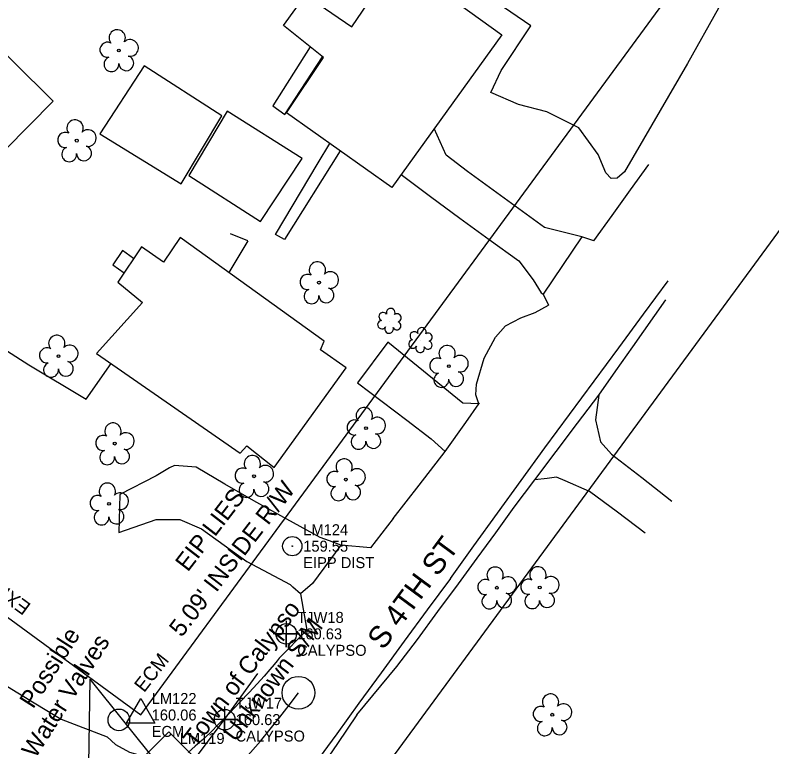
# Model space of a CAD drawing. Extents: x 2262665 to 2270527, y 505476 to 514960.
# Drawn here: x 2266488 to 2266660.4, y 511638.6 to 511805.4 of the extents above; entities that cross this region are included whole.
import ezdxf

# ---------------------------------------------------------------- set-up
doc = ezdxf.new("R2010")
doc.units = 0
for name, color, linetype in [('CTL Secondary Horizontal and Vertical CELL', 7, 'Continuous'), ('CTL Secondary Horizontal and Vertical Cogo Number', 7, 'Continuous'), ('Exist Building', 7, 'Continuous'), ('Exist Building Metal Canopy', 7, 'Continuous'), ('Exist Horizontal Alignment', 7, 'Continuous'), ('Exist Other Culture Area Outline', 7, 'Continuous'), ('Exist Other Culture Fence Line', 7, 'Continuous'), ('Exist Other Culture Gate', 7, 'Continuous'), ('Exist Property Iron Pin CELL', 7, 'Continuous'), ('Exist Property Iron Pin Cogo Comment', 7, 'Continuous'), ('Exist Property Iron Pin Cogo Elevation', 7, 'Continuous'), ('Exist Property Iron Pin Cogo Number', 7, 'Continuous'), ('Exist Property Iron Pin Text', 7, 'Continuous'), ('Exist Right of Way Line', 7, 'Continuous'), ('Exist Right of Way Line Text', 7, 'Continuous'), ('Exist Right of Way Monument CELL', 7, 'Continuous'), ('Exist Right of Way Monument Cogo Comment', 7, 'Continuous'), ('Exist Right of Way Monument Cogo Elevation', 7, 'Continuous'), ('Exist Right of Way Monument Cogo Number', 7, 'Continuous'), ('Exist Right of Way Monument Text', 7, 'Continuous'), ('Exist Roads Change in Surface', 7, 'Continuous'), ('Exist Roads EOP', 7, 'Continuous'), ('Exist Roads EOP Other', 7, 'Continuous'), ('Exist Roads EOP Text', 7, 'Continuous'), ('Exist Roads EOT', 7, 'Continuous'), ('Exist Roads Soil', 7, 'Continuous'), ('Exist Utilities Other Located Object Leader', 7, 'Continuous'), ('Exist Utilities Other Located Object Text', 7, 'Continuous'), ('Exist Utilities Other Pole CELL', 7, 'Continuous'), ('Exist Utilities Water UG Line SUE LOS B', 7, 'Continuous'), ('Exist Utilities Water UG Line SUE LOS B Cogo Comment', 7, 'Continuous'), ('Exist Utilities Water UG Line SUE LOS B Cogo Elevation', 7, 'Continuous'), ('Exist Utilities Water UG Line SUE LOS B Cogo Number', 7, 'Continuous'), ('Exist Utilities Water UG Line SUE LOS B Cogo Point CELL', 7, 'Continuous'), ('Exist Utilities Water UG Line SUE LOS B Text', 7, 'Continuous'), ('Exist Vegetation Shrub CELL', 7, 'Continuous'), ('Exist Vegetation Tree CELL', 7, 'Continuous'), ('Exist Vegetation Woods Line', 7, 'Continuous')]:
    doc.layers.add(name, color=color, linetype=linetype)

msp = doc.modelspace()

# ---------------------------------------------------------------- linework, layer by layer
at = {"layer": 'CTL Secondary Horizontal and Vertical CELL'}
msp.add_lwpolyline([(2266517.74, 511636.81), (2266522.98, 511642.05), (2266528.23, 511636.8), (2266522.99, 511631.56)], close=True, dxfattribs=at)
at = {"layer": 'Exist Building'}
for points in [[(2266573.81, 511766.09), (2266549.82, 511783.07), (2266558.22, 511795.69), (2266549.12, 511802.96), (2266554.14, 511809.94), (2266564.69, 511802.71), (2266575.11, 511818.02), (2266598.82, 511800.85)], [(2266496.61, 511785.73), (2266478.4, 511803.76), (2266467.38, 511793.15), (2266485.72, 511774.63)], [(2266535.06, 511782.39), (2266517.34, 511793.77), (2266507.27, 511778.28), (2266525.78, 511766.89)], [(2266558.39, 511731.07), (2266525.56, 511754.65), (2266521.73, 511749.1), (2266516.74, 511752.54), (2266511.32, 511744.48), (2266516.94, 511739.91), (2266506.52, 511728.23), (2266539.25, 511705.51), (2266540.76, 511707.25), (2266547.01, 511702.31), (2266563.38, 511724.99), (2266557.52, 511729.08)]]:
    msp.add_lwpolyline(points, close=True, dxfattribs=at)
at = {"layer": 'Exist Building Metal Canopy'}
msp.add_lwpolyline([(2266553.37, 511772.67), (2266536.3, 511783.5), (2266527.52, 511768.82), (2266543.83, 511758.33), (2266553.37, 511772.67)], dxfattribs=at)
at = {"layer": 'Exist Horizontal Alignment'}
msp.add_circle((2266552.51, 511650.94), 3.75, dxfattribs=at)
msp.add_arc((2266391.27, 511769.26), 200, 291.7907, 323.7279, dxfattribs=at)
at = {"layer": 'Exist Other Culture Area Outline'}
for points in [[(2266555.2, 511798.11), (2266546.64, 511784.7), (2266549.37, 511782.69), (2266558.01, 511795.86)], [(2266561.99, 511774.46), (2266549.3, 511754.19), (2266547.27, 511755.4), (2266557.01, 511771.71), (2266559.67, 511776.1)], [(2266514.95, 511749.87), (2266512.39, 511751.7), (2266510.22, 511748.42), (2266512.78, 511746.66)]]:
    msp.add_lwpolyline(points, dxfattribs=at)
at = {"layer": 'Exist Other Culture Fence Line'}
msp.add_line((2266540.95, 511753.94), (2266536.66, 511746.68), dxfattribs=at)
msp.add_lwpolyline([(2266466.2, 511742.68), (2266471.66, 511740.59), (2266480.22, 511732.61), (2266491.1, 511725.68), (2266504.15, 511717.81), (2266509.81, 511725.95)], dxfattribs=at)
at = {"layer": 'Exist Other Culture Gate'}
msp.add_line((2266540.95, 511753.94), (2266537, 511755.53), dxfattribs=at)
at = {"layer": 'Exist Property Iron Pin CELL'}
for radius in [2.2, 0.0707]:
    msp.add_circle((2266551.1, 511684.35), radius, dxfattribs=at)
at = {"layer": 'Exist Right of Way Line'}
for p, q in [((2266516.56, 511645.89), (2266751, 511965.37)), ((2266563.3, 511621.69), (2266792.92, 511934.6)), ((2266449.11, 511695.39), (2266516.56, 511645.89))]:
    msp.add_line(p, q, dxfattribs=at)
at = {"layer": 'Exist Right of Way Monument CELL'}
msp.add_line((2266516.56, 511645.89), (2266516.56, 511645.89), dxfattribs=at)
msp.add_lwpolyline([(2266513.31, 511644), (2266516.56, 511649.64), (2266519.81, 511644)], close=True, dxfattribs=at)
at = {"layer": 'Exist Roads Change in Surface'}
for points in [[(2266617.09, 511754.8), (2266612.66, 511748.29), (2266608.23, 511741.78)], [(2266562.19, 511684.61), (2266555.74, 511675.87), (2266552.98, 511673.46)]]:
    msp.add_lwpolyline(points, dxfattribs=at)
at = {"layer": 'Exist Roads EOP'}
for points in [[(2266619.82, 511753.93), (2266623.98, 511759.72), (2266628.14, 511765.51), (2266632.3, 511771.29)], [(2266588.98, 511675.78), (2266593.22, 511681.6), (2266597.45, 511687.41), (2266601.69, 511693.23), (2266606.37, 511699.47), (2266611.22, 511705.91), (2266616.06, 511712.35), (2266620.91, 511718.78), (2266624.81, 511724.29), (2266628.7, 511729.79), (2266636.2, 511740.46)], [(2266574.07, 511690.66), (2266580, 511698.28), (2266585.93, 511705.9), (2266590.61, 511712.55), (2266593.61, 511716.79), (2266593.74, 511716.98)], [(2266574.07, 511690.66), (2266568.95, 511683.96)], [(2266565.81, 511645.9), (2266565.81, 511645.9), (2266574.94, 511656.91), (2266579.63, 511663.09), (2266584.3, 511669.43), (2266588.98, 511675.78)], [(2266554.39, 511665.22), (2266548.14, 511658.81), (2266548.14, 511658.81)], [(2266548.14, 511658.81), (2266547.69, 511658.25), (2266546.97, 511657.38), (2266545.96, 511656.22), (2266544.66, 511654.74), (2266543.09, 511653), (2266541.26, 511651.01), (2266539.16, 511648.79), (2266536.8, 511646.32), (2266534.44, 511643.91), (2266532.36, 511641.85), (2266530.54, 511640.14), (2266529, 511638.79), (2266527.35, 511637.37)], [(2266565.81, 511645.9), (2266561.38, 511639.4), (2266557.58, 511633.86), (2266554.41, 511629.27), (2266549.65, 511622.49), (2266549.53, 511622.32)]]:
    msp.add_lwpolyline(points, dxfattribs=at)
at = {"layer": 'Exist Roads EOP Other'}
msp.add_line((2266568.95, 511683.96), (2266562.19, 511684.61), dxfattribs=at)
for points in [[(2266619.82, 511753.93), (2266617.09, 511754.8), (2266608.59, 511756.96), (2266602.73, 511761.22), (2266596.88, 511765.47), (2266591.03, 511769.73), (2266586.17, 511773.41), (2266583.46, 511779.5)], [(2266575.92, 511769.02), (2266582.6, 511764.04), (2266589.28, 511759.07), (2266595.99, 511754.21), (2266602.69, 511749.36), (2266605.97, 511745.06), (2266607.78, 511742.05), (2266608.23, 511741.78), (2266609.5, 511739.28)], [(2266593.61, 511716.79), (2266592.95, 511718.81), (2266593.05, 511721.25), (2266594.81, 511727.16), (2266597.41, 511731.98), (2266599.7, 511734.53), (2266603.2, 511736.39), (2266606.44, 511737.61), (2266609.5, 511739.28)], [(2266552.98, 511673.46), (2266554.39, 511665.22)]]:
    msp.add_lwpolyline(points, dxfattribs=at)
at = {"layer": 'Exist Roads EOT'}
for points in [[(2266587.12, 511677.01), (2266592.5, 511684.45), (2266597.88, 511691.88), (2266603.26, 511699.32), (2266608.64, 511706.76), (2266614.26, 511714.37), (2266619.88, 511721.97), (2266625.51, 511729.58), (2266631.13, 511737.19), (2266636.76, 511744.79)], [(2266587.12, 511677.01), (2266581.86, 511669.84), (2266576.61, 511662.67), (2266571.35, 511655.5), (2266566.29, 511648.56), (2266561.22, 511641.61), (2266556.16, 511634.67), (2266551.09, 511627.72), (2266548.04, 511623.6)]]:
    msp.add_lwpolyline(points, dxfattribs=at)
at = {"layer": 'Exist Roads Soil'}
for p, q in [((2266562.19, 511684.61), (2266562.19, 511684.61)), ((2266552.98, 511673.46), (2266551.25, 511675.03))]:
    msp.add_line(p, q, dxfattribs=at)
for points in [[(2266593.61, 511716.79), (2266589.95, 511716.94), (2266584.25, 511721.56), (2266578.55, 511726.19), (2266572.84, 511730.81), (2266565.97, 511721.56), (2266571.57, 511717.31), (2266577.18, 511713.05), (2266582.78, 511708.8), (2266585.93, 511705.9)], [(2266620.91, 511718.78), (2266620.19, 511713.14), (2266621.34, 511708.09), (2266623.85, 511705.31), (2266630.73, 511699.96), (2266637.6, 511694.6)], [(2266562.19, 511684.61), (2266559.61, 511685.55), (2266557.43, 511686.35), (2266549.87, 511690.51), (2266542.32, 511694.68), (2266535.74, 511698.5), (2266529.17, 511702.32), (2266524.28, 511702.7), (2266523.11, 511702.19), (2266520.1, 511700.4)], [(2266520.1, 511700.4), (2266511.81, 511696.15), (2266511.58, 511687.5), (2266520.12, 511690.41), (2266525.5, 511690.42), (2266530.4, 511688.29), (2266540.78, 511680.85), (2266550.64, 511675.59), (2266551.25, 511675.03)], [(2266631.53, 511687.35), (2266625.18, 511692.08), (2266618.83, 511696.8), (2266613.25, 511699.26), (2266611.33, 511700.05), (2266609.14, 511699.75), (2266606.37, 511699.47)], [(2266465.71, 511662.82), (2266470.41, 511659.42), (2266478.29, 511655.89), (2266486.18, 511652.36), (2266492.31, 511648.66), (2266498.44, 511644.96), (2266508.95, 511640.94)], [(2266508.95, 511640.94), (2266510.82, 511639.18), (2266514.01, 511637.42), (2266516.96, 511636.54), (2266519.34, 511636.1), (2266522.03, 511635.87), (2266525.83, 511636.42)]]:
    msp.add_lwpolyline(points, dxfattribs=at)
at = {"layer": 'Exist Utilities Other Located Object Leader'}
for p in [(2266504.33, 511608.41), (2266532.76, 511619.63)]:
    msp.add_line(p, (2266505.05, 511654.01), dxfattribs=at)
at = {"layer": 'Exist Utilities Other Pole CELL'}
msp.add_circle((2266511.59, 511644.77), 2.46, dxfattribs=at)
at = {"layer": 'Exist Utilities Water UG Line SUE LOS B'}
msp.add_lwpolyline([(2266489.05, 511579.09), (2266496.16, 511589.74), (2266506.6, 511604.6), (2266522.73, 511627.69), (2266535.69, 511644.83), (2266543.26, 511655.36)], dxfattribs=at)
at = {"layer": 'Exist Utilities Water UG Line SUE LOS B Cogo Point CELL'}
for points in [[(2266549.73, 511667.37), (2266549.73, 511661.37), (2266549.73, 511664.37), (2266552.73, 511664.37), (2266546.73, 511664.37)], [(2266535.69, 511647.83), (2266535.69, 511641.83), (2266535.69, 511644.83), (2266538.69, 511644.83), (2266532.69, 511644.83)]]:
    msp.add_lwpolyline(points, dxfattribs=at)
for centre in [(2266549.73, 511664.37), (2266535.69, 511644.83)]:
    msp.add_circle(centre, 2.34, dxfattribs=at)
at = {"layer": 'Exist Vegetation Shrub CELL'}
for p, q in [((2266573.29, 511735.51), (2266573.29, 511735.51)), ((2266580.37, 511731.11), (2266580.37, 511731.11))]:
    msp.add_line(p, q, dxfattribs=at)
for centre, radius, start, end in [((2266573.52, 511737.55), 0.99, 334.8391, 200.4717), ((2266571.81, 511736.64), 0.968, 35.8908, 245.4216), ((2266574.97, 511736.38), 0.929, 284.4567, 126.0861), ((2266571.49, 511734.81), 0.955, 95.1099, 327.9534), ((2266574.93, 511734.58), 0.937, 204.9913, 73.4601), ((2266573.17, 511733.83), 0.984, 151.2797, 21.387), ((2266578.89, 511732.24), 0.968, 35.8908, 245.4216), ((2266580.6, 511733.15), 0.99, 334.8391, 200.4717), ((2266582.04, 511731.98), 0.929, 284.4567, 126.0861), ((2266578.57, 511730.4), 0.955, 95.1099, 327.9534), ((2266582.01, 511730.18), 0.937, 204.9913, 73.4601), ((2266580.24, 511729.43), 0.984, 151.2797, 21.387)]:
    msp.add_arc(centre, radius, start, end, dxfattribs=at)
at = {"layer": 'Exist Vegetation Tree CELL'}
for p, q in [((2266511.59, 511797.29), (2266511.59, 511797.29)), ((2266501.98, 511776.75), (2266501.98, 511776.75)), ((2266557.19, 511744.4), (2266557.19, 511744.4)), ((2266497.84, 511727.66), (2266497.84, 511727.66)), ((2266586.76, 511725.35), (2266586.76, 511725.35)), ((2266567.9, 511711.23), (2266567.9, 511711.23)), ((2266510.64, 511707.71), (2266510.64, 511707.71)), ((2266542.39, 511700.28), (2266542.39, 511700.28)), ((2266563.3, 511699.51), (2266563.3, 511699.51)), ((2266509.35, 511694), (2266509.35, 511694)), ((2266597.71, 511674.88), (2266597.71, 511674.88)), ((2266607.47, 511674.93), (2266607.47, 511674.93)), ((2266610.33, 511645.95), (2266610.33, 511645.95))]:
    msp.add_line(p, q, dxfattribs=at)
for centre in [(2266511.59, 511797.29), (2266501.98, 511776.75), (2266557.19, 511744.4), (2266497.84, 511727.66), (2266586.76, 511725.35), (2266567.9, 511711.23), (2266510.64, 511707.71), (2266542.39, 511700.28), (2266563.3, 511699.51), (2266509.35, 511694), (2266597.71, 511674.88), (2266607.47, 511674.93), (2266610.33, 511645.95)]:
    msp.add_circle(centre, 0.326, dxfattribs=at)
for centre, radius, start, end in [((2266511.21, 511800.17), 1.86, 330.1651, 219.7134), ((2266508.99, 511797.45), 1.73, 62.6636, 279.3457), ((2266514.14, 511797.88), 1.9, 257.1011, 134.1999), ((2266509.89, 511794.17), 1.69, 111.5671, 6.231), ((2266513.27, 511794.39), 1.7, 181.2822, 74.56), ((2266501.6, 511779.63), 1.86, 330.1651, 219.7134), ((2266499.38, 511776.91), 1.73, 62.6636, 279.3457), ((2266504.53, 511777.34), 1.9, 257.1011, 134.1999), ((2266500.28, 511773.63), 1.69, 111.5671, 6.231), ((2266503.66, 511773.86), 1.7, 181.2822, 74.56), ((2266556.81, 511747.28), 1.86, 330.1651, 219.7134), ((2266559.74, 511744.99), 1.9, 257.1011, 134.1999), ((2266554.59, 511744.56), 1.73, 62.6636, 279.3457), ((2266558.87, 511741.51), 1.7, 181.2822, 74.56), ((2266555.49, 511741.28), 1.69, 111.5671, 6.231), ((2266497.45, 511730.54), 1.86, 330.1651, 219.7134), ((2266495.23, 511727.82), 1.73, 62.6636, 279.3457), ((2266500.39, 511728.25), 1.9, 257.1011, 134.1999), ((2266586.38, 511728.22), 1.86, 330.1651, 219.7134), ((2266589.31, 511725.94), 1.9, 257.1011, 134.1999), ((2266496.13, 511724.54), 1.69, 111.5671, 6.231), ((2266499.51, 511724.76), 1.7, 181.2822, 74.56), ((2266584.16, 511725.5), 1.73, 62.6636, 279.3457), ((2266585.06, 511722.23), 1.69, 111.5671, 6.231), ((2266588.43, 511722.45), 1.7, 181.2822, 74.56), ((2266567.51, 511714.11), 1.86, 330.1651, 219.7134), ((2266510.25, 511710.58), 1.86, 330.1651, 219.7134), ((2266565.29, 511711.39), 1.73, 62.6636, 279.3457), ((2266570.45, 511711.82), 1.9, 257.1011, 134.1999), ((2266508.03, 511707.86), 1.73, 62.6636, 279.3457), ((2266513.19, 511708.3), 1.9, 257.1011, 134.1999), ((2266566.19, 511708.11), 1.69, 111.5671, 6.231), ((2266569.57, 511708.33), 1.7, 181.2822, 74.56), ((2266508.93, 511704.59), 1.69, 111.5671, 6.231), ((2266512.31, 511704.81), 1.7, 181.2822, 74.56), ((2266542, 511703.15), 1.86, 330.1651, 219.7134), ((2266562.92, 511702.38), 1.86, 330.1651, 219.7134), ((2266539.78, 511700.43), 1.73, 62.6636, 279.3457), ((2266544.94, 511700.86), 1.9, 257.1011, 134.1999), ((2266565.85, 511700.1), 1.9, 257.1011, 134.1999), ((2266560.7, 511699.66), 1.73, 62.6636, 279.3457), ((2266508.96, 511696.88), 1.86, 330.1651, 219.7134), ((2266540.68, 511697.16), 1.69, 111.5671, 6.231), ((2266544.06, 511697.38), 1.7, 181.2822, 74.56), ((2266564.97, 511696.61), 1.7, 181.2822, 74.56), ((2266561.6, 511696.39), 1.69, 111.5671, 6.231), ((2266506.74, 511694.16), 1.73, 62.6636, 279.3457), ((2266511.9, 511694.59), 1.9, 257.1011, 134.1999), ((2266507.64, 511690.88), 1.69, 111.5671, 6.231), ((2266511.02, 511691.1), 1.7, 181.2822, 74.56), ((2266597.32, 511677.75), 1.86, 330.1651, 219.7134), ((2266607.08, 511677.81), 1.86, 330.1651, 219.7134), ((2266595.1, 511675.03), 1.73, 62.6636, 279.3457), ((2266600.26, 511675.47), 1.9, 257.1011, 134.1999), ((2266604.86, 511675.09), 1.73, 62.6636, 279.3457), ((2266610.02, 511675.52), 1.9, 257.1011, 134.1999), ((2266596, 511671.76), 1.69, 111.5671, 6.231), ((2266599.38, 511671.98), 1.7, 181.2822, 74.56), ((2266605.77, 511671.81), 1.69, 111.5671, 6.231), ((2266609.14, 511672.04), 1.7, 181.2822, 74.56), ((2266609.94, 511648.83), 1.86, 330.1651, 219.7134), ((2266612.88, 511646.54), 1.9, 257.1011, 134.1999), ((2266607.72, 511646.11), 1.73, 62.6636, 279.3457), ((2266608.62, 511642.83), 1.69, 111.5671, 6.231), ((2266612, 511643.06), 1.7, 181.2822, 74.56)]:
    msp.add_arc(centre, radius, start, end, dxfattribs=at)
at = {"layer": 'Exist Vegetation Woods Line'}
msp.add_lwpolyline([(2266648.19, 511806.95), (2266641.12, 511794.35), (2266626.77, 511769.66), (2266625.15, 511768.17), (2266623.72, 511768.16), (2266622.57, 511769.45), (2266620.77, 511773.62), (2266616.38, 511779.67), (2266609.08, 511783.34), (2266602.66, 511784.97), (2266596.36, 511787.75), (2266598.71, 511792.74), (2266605.44, 511802.95), (2266581.23, 511819.57)], dxfattribs=at)

# ---------------------------------------------------------------- texts
at = {"layer": 'CTL Secondary Horizontal and Vertical Cogo Number'}
msp.add_text('LM119', height=2.5, dxfattribs=at).set_placement((2266525.45, 511639.29))
at = {"layer": 'Exist Property Iron Pin Cogo Comment'}
msp.add_text('EIPP DIST', height=2.5, dxfattribs=at).set_placement((2266553.6, 511679.35))
at = {"layer": 'Exist Property Iron Pin Cogo Elevation'}
msp.add_text('159.55', height=2.5, dxfattribs=at).set_placement((2266553.6, 511683.1))
at = {"layer": 'Exist Property Iron Pin Cogo Number'}
msp.add_text('LM124', height=2.5, dxfattribs=at).set_placement((2266553.6, 511686.85))
at = {"layer": 'Exist Property Iron Pin Text'}
for s, p in [("5.09' INSIDE R/W", (2266525.89, 511663.41)), ('EIP LIES', (2266527.29, 511678.32))]:
    msp.add_text(s, height=4, rotation=52.3543, dxfattribs=at).set_placement(p)
at = {"layer": 'Exist Right of Way Line Text'}
msp.add_text('EXISTING R/W', height=3.2, rotation=143.7279, dxfattribs=at).set_placement((2266491.76, 511671.01))
at = {"layer": 'Exist Right of Way Monument Cogo Comment'}
msp.add_text('ECM', height=2.5, dxfattribs=at).set_placement((2266519.06, 511640.89))
at = {"layer": 'Exist Right of Way Monument Cogo Elevation'}
msp.add_text('160.06', height=2.5, dxfattribs=at).set_placement((2266519.06, 511644.64))
at = {"layer": 'Exist Right of Way Monument Cogo Number'}
msp.add_text('LM122', height=2.5, dxfattribs=at).set_placement((2266519.06, 511648.39))
at = {"layer": 'Exist Right of Way Monument Text'}
msp.add_text('ECM', height=3.2, rotation=51.9286, dxfattribs=at).set_placement((2266517.34, 511650.84))
at = {"layer": 'Exist Roads EOP Text'}
msp.add_text('S 4TH ST', height=5, rotation=53.5473, dxfattribs=at).set_placement((2266571.85, 511660.49))
at = {"layer": 'Exist Utilities Other Located Object Text'}
for s, p in [('Possible', (2266492.06, 511647.12)), ('Water Valves', (2266492.56, 511635.8))]:
    msp.add_text(s, height=4, rotation=57.4771, dxfattribs=at).set_placement(p)
at = {"layer": 'Exist Utilities Water UG Line SUE LOS B Cogo Comment'}
for p in [(2266552.23, 511659.37), (2266538.19, 511639.83)]:
    msp.add_text('CALYPSO', height=2.5, dxfattribs=at).set_placement(p)
at = {"layer": 'Exist Utilities Water UG Line SUE LOS B Cogo Elevation'}
for p in [(2266552.23, 511663.12), (2266538.19, 511643.58)]:
    msp.add_text('160.63', height=2.5, dxfattribs=at).set_placement(p)
at = {"layer": 'Exist Utilities Water UG Line SUE LOS B Cogo Number'}
for s, p in [('TJW18', (2266552.23, 511666.87)), ('TJW17', (2266538.19, 511647.33))]:
    msp.add_text(s, height=2.5, dxfattribs=at).set_placement(p)
at = {"layer": 'Exist Utilities Water UG Line SUE LOS B Text'}
for s, p in [('Town of Calypso', (2266529.11, 511638.23)), ('Unknown S/M', (2266538.22, 511639.51))]:
    msp.add_text(s, height=4, rotation=52.8872, dxfattribs=at).set_placement(p)

doc.saveas('drawing.dxf')
